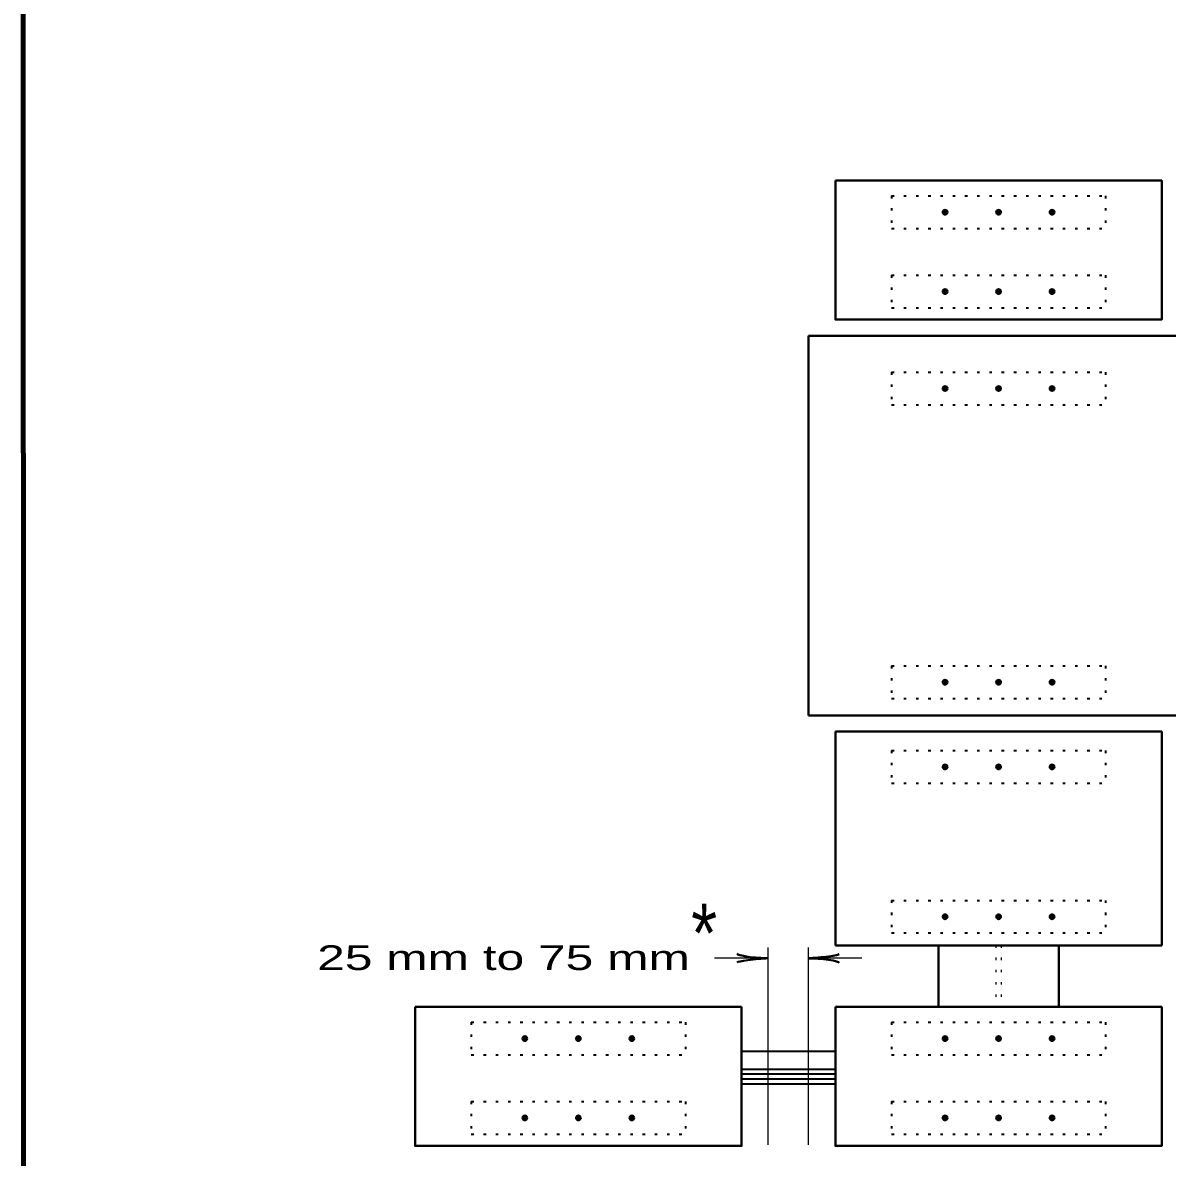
# Model space of a CAD drawing. Extents: x 851 to 1706, y -23 to 521.
# Drawn here: x 908 to 1048.4, y 164.8 to 303.9 of the extents above; entities that cross this region are included whole.
import ezdxf
from ezdxf.enums import TextEntityAlignment as Align

# ---------------------------------------------------------------- set-up
doc = ezdxf.new("R2010")
doc.units = 0
doc.linetypes.add('DOTTED', pattern=[1.5, 0.3, -1.2])
doc.layers.add('1', color=7, linetype='Continuous', lineweight=35)

msp = doc.modelspace()

# ---------------------------------------------------------------- hatches: boundary and pattern name
at = {"layer": '1'}
for points in [[(1021.412, 280.682, 1), (1020.841, 280.682, 1)], [(1027.973, 280.682, 1), (1027.402, 280.682, 1)], [(1034.534, 280.682, 1), (1033.963, 280.682, 1)], [(1021.412, 270.95, 1), (1020.841, 270.95, 1)], [(1027.973, 270.95, 1), (1027.402, 270.95, 1)], [(1034.534, 270.95, 1), (1033.963, 270.95, 1)], [(1021.412, 259.058, 1), (1020.841, 259.058, 1)], [(1027.973, 259.058, 1), (1027.402, 259.058, 1)], [(1034.534, 259.058, 1), (1033.963, 259.058, 1)], [(1021.412, 223.027, 1), (1020.841, 223.027, 1)], [(1027.973, 223.027, 1), (1027.402, 223.027, 1)], [(1034.534, 223.027, 1), (1033.963, 223.027, 1)], [(1021.412, 212.639, 1), (1020.841, 212.639, 1)], [(1027.973, 212.639, 1), (1027.402, 212.639, 1)], [(1034.534, 212.639, 1), (1033.963, 212.639, 1)], [(1021.412, 194.268, 1), (1020.841, 194.268, 1)], [(1027.973, 194.268, 1), (1027.402, 194.268, 1)], [(1034.534, 194.268, 1), (1033.963, 194.268, 1)], [(969.881, 179.314, 1), (969.309, 179.314, 1)], [(976.442, 179.314, 1), (975.87, 179.314, 1)], [(983.003, 179.314, 1), (982.431, 179.314, 1)], [(1021.412, 179.314, 1), (1020.841, 179.314, 1)], [(1027.973, 179.314, 1), (1027.402, 179.314, 1)], [(1034.534, 179.314, 1), (1033.963, 179.314, 1)], [(969.881, 169.582, 1), (969.309, 169.582, 1)], [(976.442, 169.582, 1), (975.87, 169.582, 1)], [(983.003, 169.582, 1), (982.431, 169.582, 1)], [(1021.412, 169.582, 1), (1020.841, 169.582, 1)], [(1027.973, 169.582, 1), (1027.402, 169.582, 1)], [(1034.534, 169.582, 1), (1033.963, 169.582, 1)]]:
    msp.add_hatch(color=256, dxfattribs=at).paths.add_polyline_path(points)

# ---------------------------------------------------------------- linework, layer by layer
at = {"layer": '1', "linetype": 'DOTTED'}
for p, q in [((1014.565, 282.677), (1040.809, 282.677)), ((1014.565, 282.677), (1014.565, 278.686)), ((1040.809, 282.677), (1040.809, 278.686)), ((1014.565, 278.686), (1040.809, 278.686)), ((1014.565, 272.945), (1040.809, 272.945)), ((1014.565, 272.945), (1014.565, 268.954)), ((1040.809, 272.945), (1040.809, 268.954)), ((1014.565, 268.954), (1040.809, 268.954)), ((1014.565, 261.053), (1040.809, 261.053)), ((1014.565, 261.053), (1014.565, 257.062)), ((1040.809, 261.053), (1040.809, 257.062)), ((1014.565, 257.062), (1040.809, 257.062)), ((1014.565, 225.023), (1040.809, 225.023)), ((1014.565, 225.023), (1014.565, 221.031)), ((1040.809, 225.023), (1040.809, 221.031)), ((1014.565, 221.031), (1040.809, 221.031)), ((1014.565, 214.634), (1040.809, 214.634)), ((1014.565, 214.634), (1014.565, 210.643)), ((1040.809, 214.634), (1040.809, 210.643)), ((1014.565, 210.643), (1040.809, 210.643)), ((1014.565, 196.264), (1040.809, 196.264)), ((1014.565, 196.264), (1014.565, 192.272)), ((1040.809, 196.264), (1040.809, 192.272)), ((1014.565, 192.272), (1040.809, 192.272)), ((963.034, 181.31), (989.278, 181.31)), ((963.034, 181.31), (963.034, 177.319)), ((989.278, 181.31), (989.278, 177.319)), ((1014.565, 181.31), (1040.809, 181.31)), ((1014.565, 181.31), (1014.565, 177.319)), ((1040.809, 181.31), (1040.809, 177.319)), ((963.034, 177.319), (989.278, 177.319)), ((1014.565, 177.319), (1040.809, 177.319)), ((963.034, 171.578), (989.278, 171.578)), ((963.034, 171.578), (963.034, 167.586)), ((989.278, 171.578), (989.278, 167.586)), ((1014.565, 171.578), (1040.809, 171.578)), ((1014.565, 171.578), (1014.565, 167.586)), ((1040.809, 171.578), (1040.809, 167.586)), ((963.034, 167.586), (989.278, 167.586)), ((1014.565, 167.586), (1040.809, 167.586))]:
    msp.add_line(p, q, dxfattribs=at)
at = {"layer": '1', "linetype": 'DOTTED', "lineweight": 25}
for p, q in [((1040.809, 282.677), (1040.809, 278.686)), ((1040.809, 225.023), (1040.809, 221.031)), ((1040.809, 214.634), (1040.809, 210.643)), ((1040.809, 196.264), (1040.809, 192.3)), ((1040.809, 196.264), (1040.809, 192.272)), ((1027.359, 190.741), (1027.359, 183.196)), ((1028.015, 190.741), (1028.015, 183.196)), ((1040.809, 181.31), (1040.809, 177.319))]:
    msp.add_line(p, q, dxfattribs=at)
at = {"layer": '1', "lineweight": 40}
for p, q in [((1050.979, 265.537), (1004.396, 265.537)), ((1004.396, 265.537), (1004.396, 218.954)), ((1050.979, 218.954), (1004.396, 218.954)), ((1007.676, 190.741), (1007.676, 216.985)), ((1047.698, 216.985), (1007.676, 216.985)), ((1007.676, 216.985), (1007.676, 190.741)), ((1047.698, 190.741), (1047.698, 216.985)), ((1047.698, 190.741), (1047.698, 216.985)), ((1047.698, 190.741), (1007.676, 190.741)), ((1047.698, 190.741), (1007.676, 190.741)), ((1020.306, 190.741), (1020.306, 183.196)), ((1035.068, 190.741), (1035.068, 183.196)), ((996.167, 183.196), (956.145, 183.196))]:
    msp.add_line(p, q, dxfattribs=at)
at = {"layer": '1', "lineweight": 25}
for p, q in [((999.448, 166.29), (999.448, 190.472)), ((1004.396, 166.29), (1004.396, 190.472)), ((999.394, 189.159), (992.833, 189.159)), ((1010.93, 189.159), (1004.369, 189.159))]:
    msp.add_line(p, q, dxfattribs=at)
at = {"layer": '1'}
for p, q in [((996.167, 177.756), (1007.676, 177.756)), ((996.167, 175.542), (1007.676, 175.542)), ((1007.676, 174.94), (996.167, 174.94)), ((1007.676, 174.339), (996.167, 174.339)), ((996.167, 173.765), (1007.676, 173.765))]:
    msp.add_line(p, q, dxfattribs=at)
at = {"layer": '1', "lineweight": 158}
msp.add_lwpolyline([(1699.744, 514.252), (908.044, 514.152), (908.144, -11.848)], dxfattribs=at)
at = {"layer": '1', "lineweight": 40}
for points in [[(1007.676, 284.564), (1047.698, 284.564), (1047.698, 267.505), (1007.676, 267.505)], [(1007.676, 183.196), (1047.698, 183.196), (1047.698, 166.138), (1007.676, 166.138)]]:
    msp.add_lwpolyline(points, close=True, dxfattribs=at)
msp.add_lwpolyline([(956.145, 183.196), (956.145, 166.138), (996.167, 166.138), (996.167, 183.196)], dxfattribs=at)
for centre in [(1021.126, 280.682), (1027.687, 280.682), (1034.248, 280.682), (1021.126, 270.95), (1027.687, 270.95), (1034.248, 270.95), (1021.126, 259.058), (1027.687, 259.058), (1034.248, 259.058), (1021.126, 223.027), (1027.687, 223.027), (1034.248, 223.027), (1021.126, 212.639), (1027.687, 212.639), (1034.248, 212.639), (1021.126, 194.268), (1027.687, 194.268), (1034.248, 194.268), (969.595, 179.314), (976.156, 179.314), (982.717, 179.314), (1021.126, 179.314), (1027.687, 179.314), (1034.248, 179.314), (969.595, 169.582), (976.156, 169.582), (982.717, 169.582), (1021.126, 169.582), (1027.687, 169.582), (1034.248, 169.582)]:
    msp.add_circle(centre, 0.286, dxfattribs=at)
for centre, major_axis, ratio, start_param, end_param in [((997.974, 189.528), (2.343, -0.205), 0.122415, 3.1415927, 5.386832), ((1005.849, 189.443), (-2.305, -0.23), 0.07063, 0.8650754, 3.1424706), ((1005.849, 189.443), (-2.305, -0.23), 0.07063, 0.8650754, 3.1424706), ((997.936, 188.888), (2.305, 0.23), 0.07063, 0.8650754, 3.1424706), ((1005.811, 188.803), (-2.343, 0.205), 0.122415, 3.1415927, 5.386832), ((1005.811, 188.803), (-2.343, 0.205), 0.122415, 3.1415927, 5.386832)]:
    msp.add_ellipse(centre, major_axis=major_axis, ratio=ratio, start_param=start_param, end_param=end_param, dxfattribs=at)

# ---------------------------------------------------------------- texts
at = {"layer": '1'}
for s, height, width, p in [('*', 7.2, 0.85, (991.583, 188.65)), ('25 mm to 75 mm', 3.037, 1.5, (966.98, 187.722))]:
    msp.add_text(s, height=height, dxfattribs=dict(at, width=width)).set_placement(p, align=Align.CENTER)

doc.saveas('drawing.dxf')
